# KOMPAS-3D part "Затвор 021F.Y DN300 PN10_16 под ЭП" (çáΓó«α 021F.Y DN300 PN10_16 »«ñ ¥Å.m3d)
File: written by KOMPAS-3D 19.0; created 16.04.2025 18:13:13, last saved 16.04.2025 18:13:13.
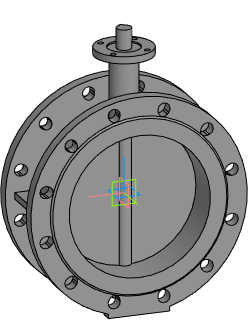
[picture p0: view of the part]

Document properties: Автор: Евгений; Полное имя файла: E:\Dendor Работа Сачек\3D для проекитирвщиков\1.6 Тип 021F.Y Затвор дисковый поворотный фланцевый\stp_Тип 021F.Y Затвор  DN40 PN10_16 под ЭП\Затвор 021F.Y DN300 PN10_16 под ЭП.m3d

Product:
- Part/product: Затвор 021F.Y DN300 PN10_16 под ЭП

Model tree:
1. Операция без истории:1  (labels: Затвор 021F.Y DN300 PN10_16 под ЭП)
